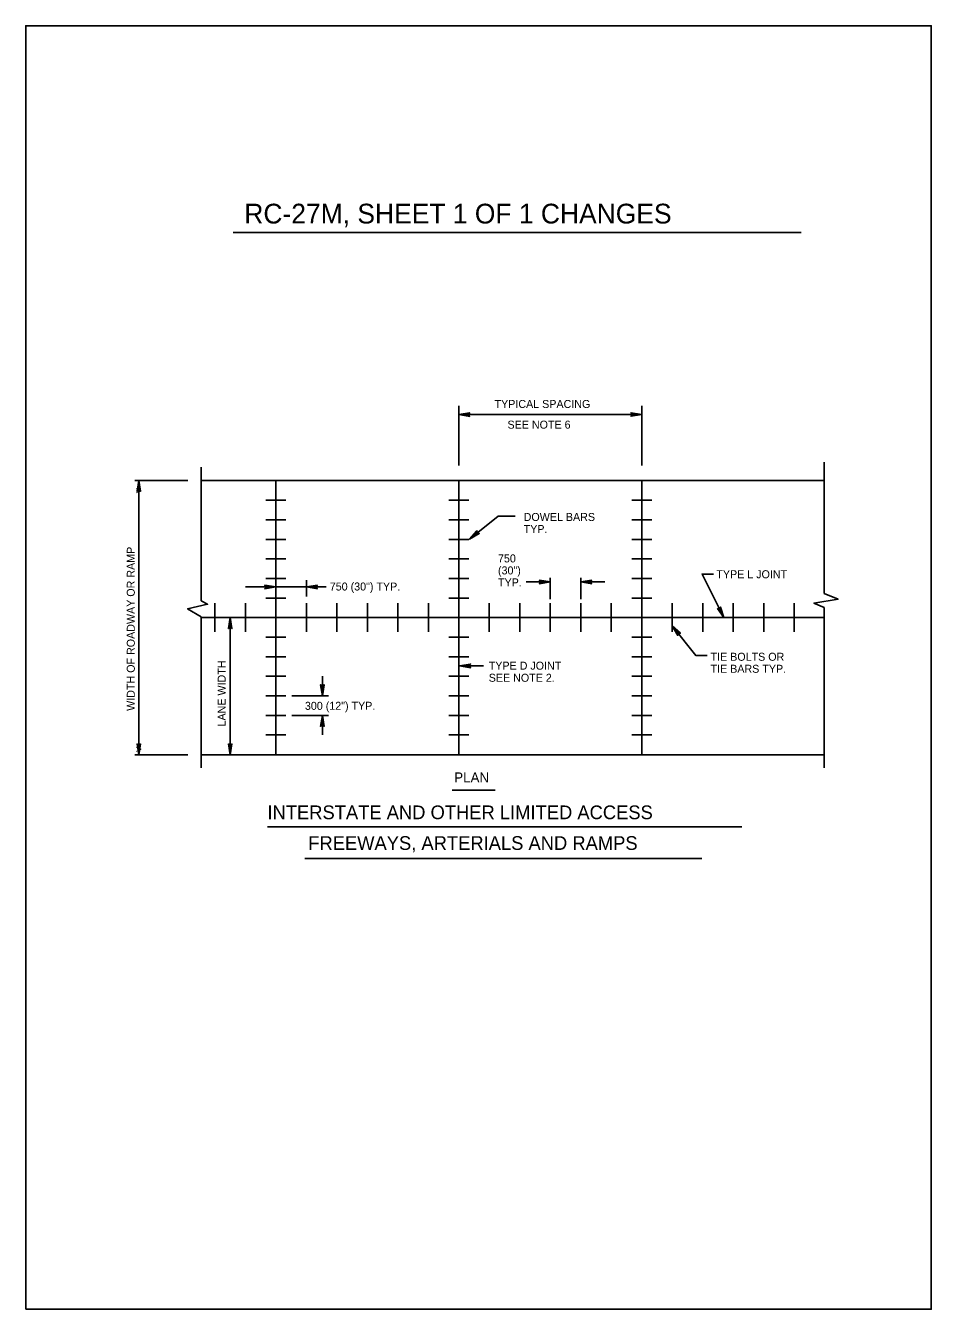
# Model space of a CAD drawing. Extents: x 637877 to 639321, y 297902 to 299090.
# Drawn here: x 637876.8 to 638173.8, y 298467.3 to 298888.3 of the extents above; entities that cross this region are included whole.
import ezdxf

# ---------------------------------------------------------------- set-up
doc = ezdxf.new("R2010")
doc.units = 0
for name, color, linetype in [('1', 7, 'Continuous'), ('2', 7, 'Continuous'), ('3', 7, 'Continuous')]:
    doc.layers.add(name, color=color, linetype=linetype)

msp = doc.modelspace()

# ---------------------------------------------------------------- linework, layer by layer
at = {"layer": '1'}
msp.add_lwpolyline([(637876.85, 298467.27), (637876.85, 298888.27), (638173.85, 298888.27), (638173.85, 298467.27)], close=True, dxfattribs=at)
for points in [[(638025.34, 298721.72), (638025.08, 298721.84), (638022.36, 298719.91), (638025.34, 298721.72), (638025.57, 298721.71), (638022.36, 298719.91), (638024.86, 298722.11), (638024.81, 298722.38), (638022.36, 298719.91), (638024.85, 298722.62), (638024.81, 298722.38)], [(637955.44, 298704.61), (637955.57, 298704.36), (637958.9, 298704.18), (637955.44, 298704.61), (637955.26, 298704.77), (637958.9, 298704.18), (637955.57, 298704.02), (637955.45, 298703.77), (637958.9, 298704.18), (637955.26, 298703.6), (637955.45, 298703.77)], [(637972.36, 298703.75), (637972.23, 298704), (637968.9, 298704.18), (637972.36, 298703.75), (637972.54, 298703.59), (637968.9, 298704.18), (637972.23, 298704.35), (637972.35, 298704.59), (637968.9, 298704.18), (637972.54, 298704.76), (637972.35, 298704.59)], [(638022.57, 298677.86), (638022.44, 298678.12), (638019.11, 298678.3), (638022.57, 298677.86), (638022.75, 298677.71), (638019.11, 298678.3), (638022.44, 298678.46), (638022.56, 298678.71), (638019.11, 298678.3), (638022.75, 298678.88), (638022.56, 298678.71)], [(637974.58, 298671.94), (637974.33, 298671.81), (637974.15, 298668.48), (637974.58, 298671.94), (637974.73, 298672.11), (637974.15, 298668.48), (637973.98, 298671.8), (637973.73, 298671.93), (637974.15, 298668.48), (637973.57, 298672.11), (637973.73, 298671.93)], [(637973.71, 298658.6), (637973.96, 298658.73), (637974.15, 298662.06), (637973.71, 298658.6), (637973.56, 298658.43), (637974.15, 298662.06), (637974.31, 298658.73), (637974.56, 298658.61), (637974.15, 298662.06), (637974.72, 298658.43), (637974.56, 298658.61)]]:
    msp.add_lwpolyline(points, dxfattribs=at)
at = {"layer": '2'}
for p, q in [((638018.9, 298743.99), (638018.9, 298763.59)), ((638078.9, 298743.99), (638078.9, 298763.59)), ((638018.9, 298760.72), (638078.9, 298760.72)), ((637934.45, 298743.49), (637934.45, 298699.61)), ((638138.67, 298745.14), (638138.67, 298702.02)), ((637930.07, 298739.13), (637912.63, 298739.13)), ((637913.94, 298739.13), (637913.94, 298649.13)), ((637934.45, 298739.13), (638138.67, 298739.13)), ((637958.9, 298739.13), (637958.9, 298649.13)), ((638018.9, 298739.13), (638018.9, 298649.13)), ((638078.9, 298739.13), (638078.9, 298649.13)), ((638031.8, 298727.39), (638022.36, 298719.91)), ((638037.37, 298727.39), (638031.8, 298727.39)), ((637948.9, 298704.18), (637958.9, 298704.18)), ((637968.9, 298704.18), (637958.9, 298704.18)), ((637968.9, 298706.43), (637968.9, 298701.03)), ((637968.9, 298704.18), (637975.43, 298704.18)), ((638048.9, 298705.82), (638041.03, 298705.82)), ((638048.9, 298700.13), (638048.9, 298707.13)), ((638058.9, 298700.13), (638058.9, 298707.13)), ((638066.78, 298705.82), (638058.9, 298705.82)), ((638138.67, 298697.5), (638138.67, 298644.87)), ((637934.45, 298694.38), (637934.45, 298644.81)), ((637934.45, 298694.13), (638138.67, 298694.13)), ((637943.9, 298694.13), (637943.9, 298649.13)), ((637974.15, 298674.89), (637974.15, 298668.48)), ((638026.99, 298678.3), (638019.11, 298678.3)), ((637976.14, 298668.48), (637964.16, 298668.48)), ((637976.14, 298662.06), (637964.16, 298662.06)), ((637974.15, 298662.06), (637974.15, 298655.65)), ((637930.07, 298649.13), (637912.63, 298649.13)), ((637934.45, 298649.13), (638138.67, 298649.13)), ((637939.31, 298649.13), (637949.58, 298649.13))]:
    msp.add_line(p, q, dxfattribs=at)
for points in [[(638022.31, 298760.29), (638022.18, 298760.54), (638018.9, 298760.72), (638022.31, 298760.29), (638022.48, 298760.14), (638018.9, 298760.72), (638022.18, 298760.88), (638022.3, 298761.13), (638018.9, 298760.72), (638022.48, 298761.29), (638022.3, 298761.13)], [(638075.5, 298761.15), (638075.62, 298760.9), (638078.9, 298760.72), (638075.5, 298761.15), (638075.32, 298761.3), (638078.9, 298760.72), (638075.63, 298760.56), (638075.51, 298760.32), (638078.9, 298760.72), (638075.32, 298760.15), (638075.51, 298760.32)], [(637913.51, 298735.73), (637913.76, 298735.85), (637913.94, 298739.13), (637913.51, 298735.73), (637913.36, 298735.55), (637913.94, 298739.13), (637914.1, 298735.86), (637914.35, 298735.74), (637913.94, 298739.13), (637914.51, 298735.55), (637914.35, 298735.74)], [(637962.19, 298732.62), (637955.61, 298732.62)], [(638022.19, 298732.62), (638015.61, 298732.62)], [(638082.19, 298732.62), (638075.61, 298732.62)], [(637962.19, 298726.2), (637958.9, 298726.2), (637955.61, 298726.2)], [(638022.19, 298726.2), (638018.9, 298726.2), (638015.61, 298726.2)], [(638082.19, 298726.2), (638078.9, 298726.2), (638075.61, 298726.2)], [(637962.19, 298719.79), (637955.61, 298719.79)], [(638022.19, 298719.79), (638015.61, 298719.79)], [(638082.19, 298719.79), (638075.61, 298719.79)], [(637962.19, 298713.37), (637958.9, 298713.37), (637955.61, 298713.37)], [(638022.19, 298713.37), (638018.9, 298713.37), (638015.61, 298713.37)], [(638082.19, 298713.37), (638078.9, 298713.37), (638075.61, 298713.37)], [(638102.42, 298708.42), (638098.67, 298708.42), (638105.85, 298694.13)], [(637962.19, 298706.96), (637955.61, 298706.96)], [(638022.19, 298706.96), (638015.61, 298706.96)], [(638045.5, 298706.24), (638045.62, 298706), (638048.9, 298705.82), (638045.5, 298706.24), (638045.32, 298706.39), (638048.9, 298705.82), (638045.63, 298705.66), (638045.51, 298705.41), (638048.9, 298705.82), (638045.32, 298705.25), (638045.51, 298705.41)], [(638062.31, 298705.39), (638062.18, 298705.64), (638058.9, 298705.82), (638062.31, 298705.39), (638062.48, 298705.24), (638058.9, 298705.82), (638062.18, 298705.98), (638062.3, 298706.22), (638058.9, 298705.82), (638062.48, 298706.39), (638062.3, 298706.22)], [(638082.19, 298706.96), (638075.61, 298706.96)], [(637934.45, 298699.61), (637936.53, 298698.49), (637929.95, 298697.04), (637934.45, 298694.38)], [(637962.19, 298700.55), (637958.9, 298700.55), (637955.61, 298700.55)], [(638022.19, 298700.55), (638018.9, 298700.55), (638015.61, 298700.55)], [(638082.19, 298700.55), (638078.9, 298700.55), (638075.61, 298700.55)], [(638138.67, 298702.02), (638143.26, 298700.18), (638135.34, 298698.9), (638138.67, 298697.5)], [(637938.9, 298689.44), (637938.9, 298694.13), (637938.9, 298698.82)], [(637948.9, 298689.44), (637948.9, 298694.13), (637948.9, 298698.82)], [(637968.9, 298689.44), (637968.9, 298694.13), (637968.9, 298698.82)], [(637978.9, 298689.44), (637978.9, 298694.13), (637978.9, 298698.82)], [(637988.9, 298689.44), (637988.9, 298694.13), (637988.9, 298698.82)], [(637998.9, 298689.44), (637998.9, 298694.13), (637998.9, 298698.82)], [(638008.9, 298689.44), (638008.9, 298694.13), (638008.9, 298698.82)], [(638028.9, 298689.44), (638028.9, 298694.13), (638028.9, 298698.82)], [(638038.9, 298689.44), (638038.9, 298694.13), (638038.9, 298698.82)], [(638048.9, 298689.44), (638048.9, 298694.13), (638048.9, 298698.82)], [(638058.9, 298689.44), (638058.9, 298694.13), (638058.9, 298698.82)], [(638068.9, 298689.44), (638068.9, 298694.13), (638068.9, 298698.82)], [(638088.9, 298689.44), (638088.9, 298694.13), (638088.9, 298698.82)], [(638098.9, 298689.44), (638098.9, 298694.13), (638098.9, 298698.82)], [(638104.7, 298697.37), (638104.54, 298697.14), (638105.85, 298694.13), (638104.7, 298697.37), (638104.76, 298697.59), (638105.85, 298694.13), (638104.23, 298696.99), (638103.96, 298696.98), (638105.85, 298694.13), (638103.73, 298697.08), (638103.96, 298696.98)], [(638108.9, 298689.44), (638108.9, 298694.13), (638108.9, 298698.82)], [(638118.9, 298689.44), (638118.9, 298694.13), (638118.9, 298698.82)], [(638128.9, 298689.44), (638128.9, 298694.13), (638128.9, 298698.82)], [(637943.48, 298690.73), (637943.72, 298690.85), (637943.9, 298694.13), (637943.48, 298690.73), (637943.33, 298690.55), (637943.9, 298694.13), (637944.06, 298690.86), (637944.31, 298690.74), (637943.9, 298694.13), (637944.47, 298690.55), (637944.31, 298690.74)], [(638100.32, 298681.74), (638096.57, 298681.74), (638088.9, 298691.46)], [(638090.68, 298688.52), (638090.79, 298688.77), (638088.9, 298691.46), (638090.68, 298688.52), (638090.67, 298688.29), (638088.9, 298691.46), (638091.06, 298688.99), (638091.32, 298689.04), (638088.9, 298691.46), (638091.57, 298689), (638091.32, 298689.04)], [(637962.19, 298687.72), (637958.9, 298687.72), (637955.61, 298687.72)], [(638022.19, 298687.72), (638018.9, 298687.72), (638015.61, 298687.72)], [(638082.19, 298687.72), (638078.9, 298687.72), (638075.61, 298687.72)], [(637962.19, 298681.3), (637955.61, 298681.3)], [(638022.19, 298681.3), (638015.61, 298681.3)], [(638082.19, 298681.3), (638075.61, 298681.3)], [(637962.19, 298674.89), (637958.9, 298674.89), (637955.61, 298674.89)], [(638022.19, 298674.89), (638018.9, 298674.89), (638015.61, 298674.89)], [(638082.19, 298674.89), (638078.9, 298674.89), (638075.61, 298674.89)], [(637962.19, 298668.48), (637955.61, 298668.48)], [(638022.19, 298668.48), (638015.61, 298668.48)], [(638082.19, 298668.48), (638075.61, 298668.48)], [(637962.19, 298662.06), (637958.9, 298662.06), (637955.61, 298662.06)], [(638022.19, 298662.06), (638018.9, 298662.06), (638015.61, 298662.06)], [(638082.19, 298662.06), (638078.9, 298662.06), (638075.61, 298662.06)], [(637962.19, 298655.65), (637955.61, 298655.65)], [(638022.19, 298655.65), (638015.61, 298655.65)], [(638082.19, 298655.65), (638075.61, 298655.65)], [(637914.37, 298652.54), (637914.12, 298652.41), (637913.94, 298649.13), (637914.37, 298652.54), (637914.52, 298652.71), (637913.94, 298649.13), (637913.78, 298652.41), (637913.53, 298652.53), (637913.94, 298649.13), (637913.37, 298652.71), (637913.53, 298652.53)], [(637944.33, 298652.54), (637944.08, 298652.41), (637943.9, 298649.13), (637944.33, 298652.54), (637944.48, 298652.71), (637943.9, 298649.13), (637943.74, 298652.41), (637943.5, 298652.53), (637943.9, 298649.13), (637943.33, 298652.71), (637943.5, 298652.53)]]:
    msp.add_lwpolyline(points, dxfattribs=at)
at = {"layer": '3'}
for p, q in [((637944.85, 298820.49), (638131.11, 298820.49)), ((638016.76, 298637.52), (638030.81, 298637.52)), ((637956.14, 298625.47), (638111.67, 298625.47)), ((637968.44, 298615.16), (638098.63, 298615.16))]:
    msp.add_line(p, q, dxfattribs=at)

# ---------------------------------------------------------------- texts
at = {"layer": '2'}
for s, p in [('SEE NOTE 6', (638034.86, 298756.11)), ('DOWEL BARS', (638040.16, 298725.83)), ('TYP.', (638040.16, 298721.89)), ('750', (638031.74, 298712.24)), ('(30")', (638031.74, 298708.3)), ('TYP.', (638031.74, 298704.36))]:
    msp.add_text(s, height=2.625, dxfattribs=at).set_placement(p)
for p in [(637913.06, 298736.51), (637913.06, 298651.76)]:
    msp.add_text('A', height=1.75, rotation=270, dxfattribs=at).set_placement(p)
at = {"layer": '3'}
for s, height, p in [('RC-27M, SHEET 1 OF 1 CHANGES', 6.48, (637948.55, 298823.39)), ('TYPICAL SPACING', 2.625, (638030.62, 298762.89)), ('TYPE L JOINT', 2.625, (638103.35, 298707.04)), ('750 (30") TYP.', 2.625, (637976.58, 298703.02)), ('TYPE D JOINT', 2.625, (638028.71, 298677.06)), ('TIE BOLTS OR', 2.625, (638101.45, 298679.98)), ('TIE BARS TYP.', 2.625, (638101.45, 298676.04)), ('SEE NOTE 2.', 2.625, (638028.71, 298673.09)), ('300 (12") TYP.', 2.625, (637968.42, 298663.89)), ('PLAN', 3.281, (638017.37, 298640.07)), ('INTERSTATE AND OTHER LIMITED ACCESS', 4.5, (637956.13, 298628.02)), ('FREEWAYS, ARTERIALS AND RAMPS', 4.5, (637969.52, 298617.95))]:
    msp.add_text(s, height=height, dxfattribs=at).set_placement(p)
for s, p in [('WIDTH OF ROADWAY OR RAMP', (637912.63, 298663.55)), ('LANE WIDTH', (637942.43, 298658.43))]:
    msp.add_text(s, height=2.625, rotation=90, dxfattribs=at).set_placement(p)

doc.saveas('drawing.dxf')
